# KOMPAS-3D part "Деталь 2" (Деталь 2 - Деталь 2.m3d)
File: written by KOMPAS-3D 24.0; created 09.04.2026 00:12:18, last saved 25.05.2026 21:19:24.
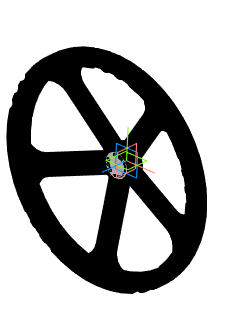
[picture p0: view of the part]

Document properties: Автор: mrdid; Полное имя файла: E:\Работа\Зайцев\АУТСОРС\Даня\GVKN1331N-2W-Fb-R Задвижка шиберная DN.ru Ду400-600 Ру4-6\исходные материалы\DN500\Деталь 2 - Деталь 2.m3d

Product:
- Body: Твердое тело1  | qty 1
    Масса: 13.775591
- Part/product: Деталь 2
    Масса: 13.775591
    additional columns: Типовые

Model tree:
1. Твердое тело1  (labels: Твердое тело1)
2. Масштабирование:1
3. Масштабирование : Твердое тело1
     Масштаб по оси Х = 1; Масштаб по оси Y = 1; Масштаб по оси Z = 1; Коэффициент = 1.5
